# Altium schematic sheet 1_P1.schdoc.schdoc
size 309 x 223 mm; Symbol: Sheet-Symbol_A4; Device: Sheet-Symbol_A4; Company: 嘉立创EDA; Version: V1.0; Page Size: A4; @Project Name: MAX31855-K-THERMOCOUPLE_METER; @Page Count: 1; @Update Date: 2024-03-21; @Create Date: 2024-03-21; @Schematic Name: Schematic1; @Page No: 1; @Page Name: P1
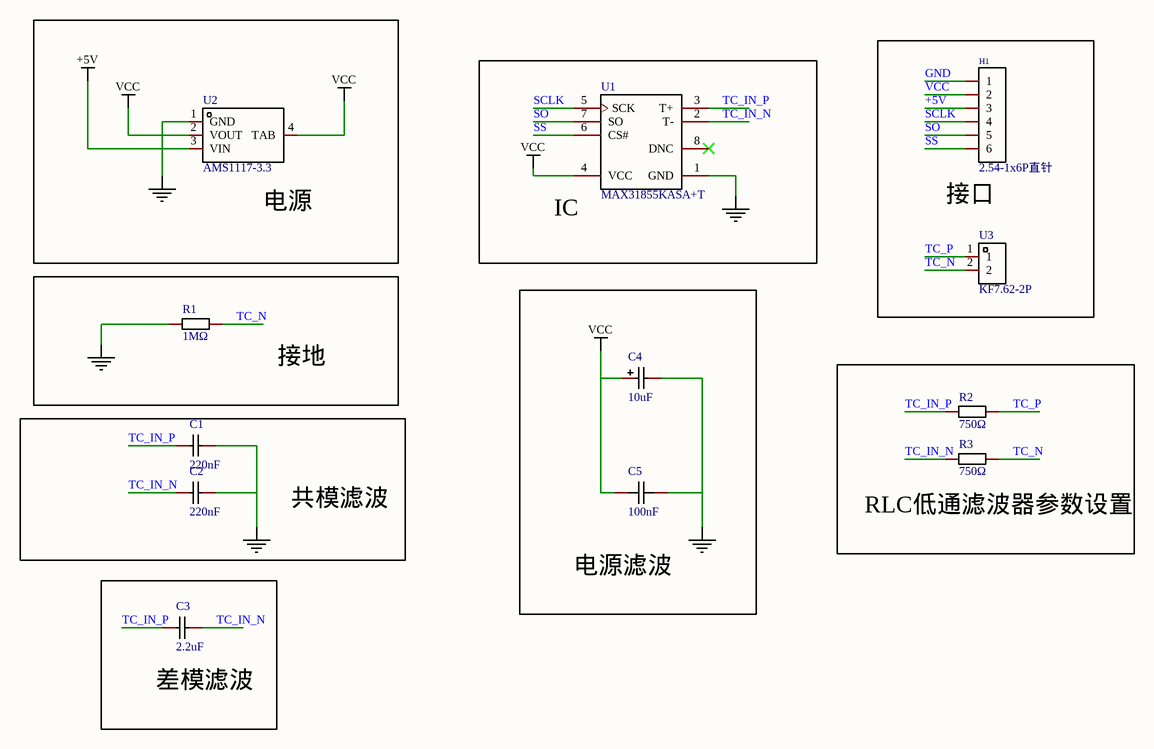
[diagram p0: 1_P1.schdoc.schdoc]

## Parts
C1  220nF  [C0603]
C2  220nF  [C0603]
C3  2.2uF  [C0603]
C4  10uF  [CAP-SMD_L3.2-W1.6-RD]
C5  100nF  [C0603]
H1  2.54-1x6P直针  [HDR-TH_6P-P2.54-V-M-1]
R1  1MΩ  [R0402]
R2  750Ω  [R0603]
R3  750Ω  [R0603]
U1  MAX31855KASA+T  [SO-8_L4.9-W3.9-P1.27-LS5.9-BL]
U2  AMS1117-3.3  [SOT-223-3_L6.5-W3.5-P3.05-LS7.0]
U3  KF7.62-2P  [CONN-TH_KF7.62-2P]

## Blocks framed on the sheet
电源: U2
接口: H1 U3
IC: U1
接地: R1
电源滤波: C4 C5
RLC低通滤波器参数设置: R2 R3
共模滤波: C1 C2
差模滤波: C3

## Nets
+5V: H1.3 U2.3(VIN)
NetC1_2: C1.2 C2.2 C4.2 C5.2 R1.1 U1.1(GND) U2.1(GND)
VCC: C4.1 C5.1 H1.2 U1.4(VCC) U2.2(VOUT) U2.4(TAB)
GND: H1.1
SCLK: H1.4 U1.5(SCK)
SO: H1.5 U1.7(SO)
SS: H1.6 U1.6(CS#)
TC_IN_N: C2.1 C3.2 R3.1 U1.2(T-)
TC_IN_P: C1.1 C3.1 R2.1 U1.3(T+)
TC_N: R1.2 R3.2 U3.2
TC_P: R2.2 U3.1

Not connected (* = marked no-connect by the designer): U1 8(DNC)*

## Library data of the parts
C1 C2 = CC0603KRX7R9BB224: Manufacturer: YAGEO(国巨); Add into BOM: yes; Tolerance: ±10%; Voltage Rated: 50V; Temperature Coefficient: X7R; Description: 容值:220nF;精度:±10%;额定电压:50V;材质(温度系数):X7R;
C3 = CL10A225KO8NNNC: Manufacturer: SAMSUNG(三星); Add into BOM: yes; Tolerance: ±10%; Voltage Rated: 16V; Temperature Coefficient: X5R; Description: 容值:2.2uF;精度:±10%;额定电压:16V;材质(温度系数):X5R;
C4 = CA45-A-16V-10uF-K: Manufacturer: CEC(振华新云); Add into BOM: yes; Tolerance: ±10%; Rated Voltage: 16V; Equivalent Series Resistance(ESR): 10Ω@100kHz; Description: 容值:10uF;精度:±10%;额定电压:16V;等效串联电阻:10Ω@100kHz;
C5 = CC0603KRX7R9BB104: Manufacturer: YAGEO(国巨); Add into BOM: yes; Tolerance: ±10%; Voltage Rated: 50V; Temperature Coefficient: X7R; Description: 容值:100nF;精度:±10%;额定电压:50V;材质(温度系数):X7R;
H1 = 2.54-1x6P直针: Manufacturer: BOOMELE(博穆精密); Symbol: Header-Male-2.54_1x6; Add into BOM: yes; Pin Structure: 1x6P; Pitch: 2.54mm; Circluar Pins/Square Pins: 方针; Current Rating (Max): 3A; Description: 插针结构:1x6P;间距:2.54mm;行距:-;圆针/方针:方针;安装类型:直插;排数:单排;总PIN位数:6P;额定电流:3A;额定电压:-;配合针长度:-;塑高:-;触头材质:黄铜;触头镀层:-;工作温度范围:-40℃~+105℃;颜色:黑色;
R1 = 0402WGF1004TCE: Manufacturer: UNI-ROYAL(厚声); Add into BOM: yes; Tolerance: ±1%; Power(Watts): 62.5mW; Overload Voltage (Max): 50V; Temperature Coefficient: ±100ppm/℃; Description: 电阻类型:厚膜电阻;阻值:1MΩ;精度:±1%;功率:62.5mW;最大工作电压:50V;温度系数:±100ppm/℃;
R2 R3 = 0603WAF7500T5E: Manufacturer: UNI-ROYAL(厚声); Add into BOM: yes; Tolerance: ±1%; Power(Watts): 100mW; Overload Voltage (Max): 75V; Temperature Coefficient: ±100ppm/℃; Description: 电阻类型:厚膜电阻;阻值:750Ω;精度:±1%;功率:100mW;最大工作电压:75V;温度系数:±100ppm/℃;
U1 = MAX31855KASA+T: Manufacturer: ADI(亚德诺)/MAXIM(美信); Add into BOM: yes; Description: 冷端补偿热电偶至数字输出转换器、高精度热电偶数字转换器IC，有效简化设计并降低系统成本
U2 = AMS1117-3.3_C5250992: Manufacturer: TWGMC(台湾迪嘉); Add into BOM: yes; Description: 输出类型：固定 输出极性：正 最大输入电压：18V 输出电压：3.3V 输出电流：1A 电源纹波抑制比(PSRR)：60dB@(120Hz)。当前应用较多领域：三端稳压器，机顶盒
U3 = KF7.62-2P: Manufacturer: KEFA(科发); Add into BOM: yes; Barrier Type: 两面; Pitch: 7.62mm; Structure: 1x2P; Pin Location: 边脚; Current Rating (Max): 24A; Voltage Rating (Max): 450V; Wire Gauge - AWG: 12~22; Wire Gauge - mm2: 2.5; Number of PINs Per Row: 2; Description: 隔板类型:两面;间距:7.62mm;结构:1x2P;安装方式:直针;引脚位置:边脚;排数:1;额定电流:24A;额定电压:450V;线规 - AWG:12~22;线规 - 平方毫米:2.5;工作温度范围:-40℃~+105℃;颜色:黑色;每排PIN数:2;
